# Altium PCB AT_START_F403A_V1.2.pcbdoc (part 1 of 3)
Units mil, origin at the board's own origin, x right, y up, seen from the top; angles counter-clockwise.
Board outline 5262.73 x 3522.74 mil, 2 copper layers (Top Layer, Bottom Layer); 135 components, 162 nets, 647 pads, 293 vias.
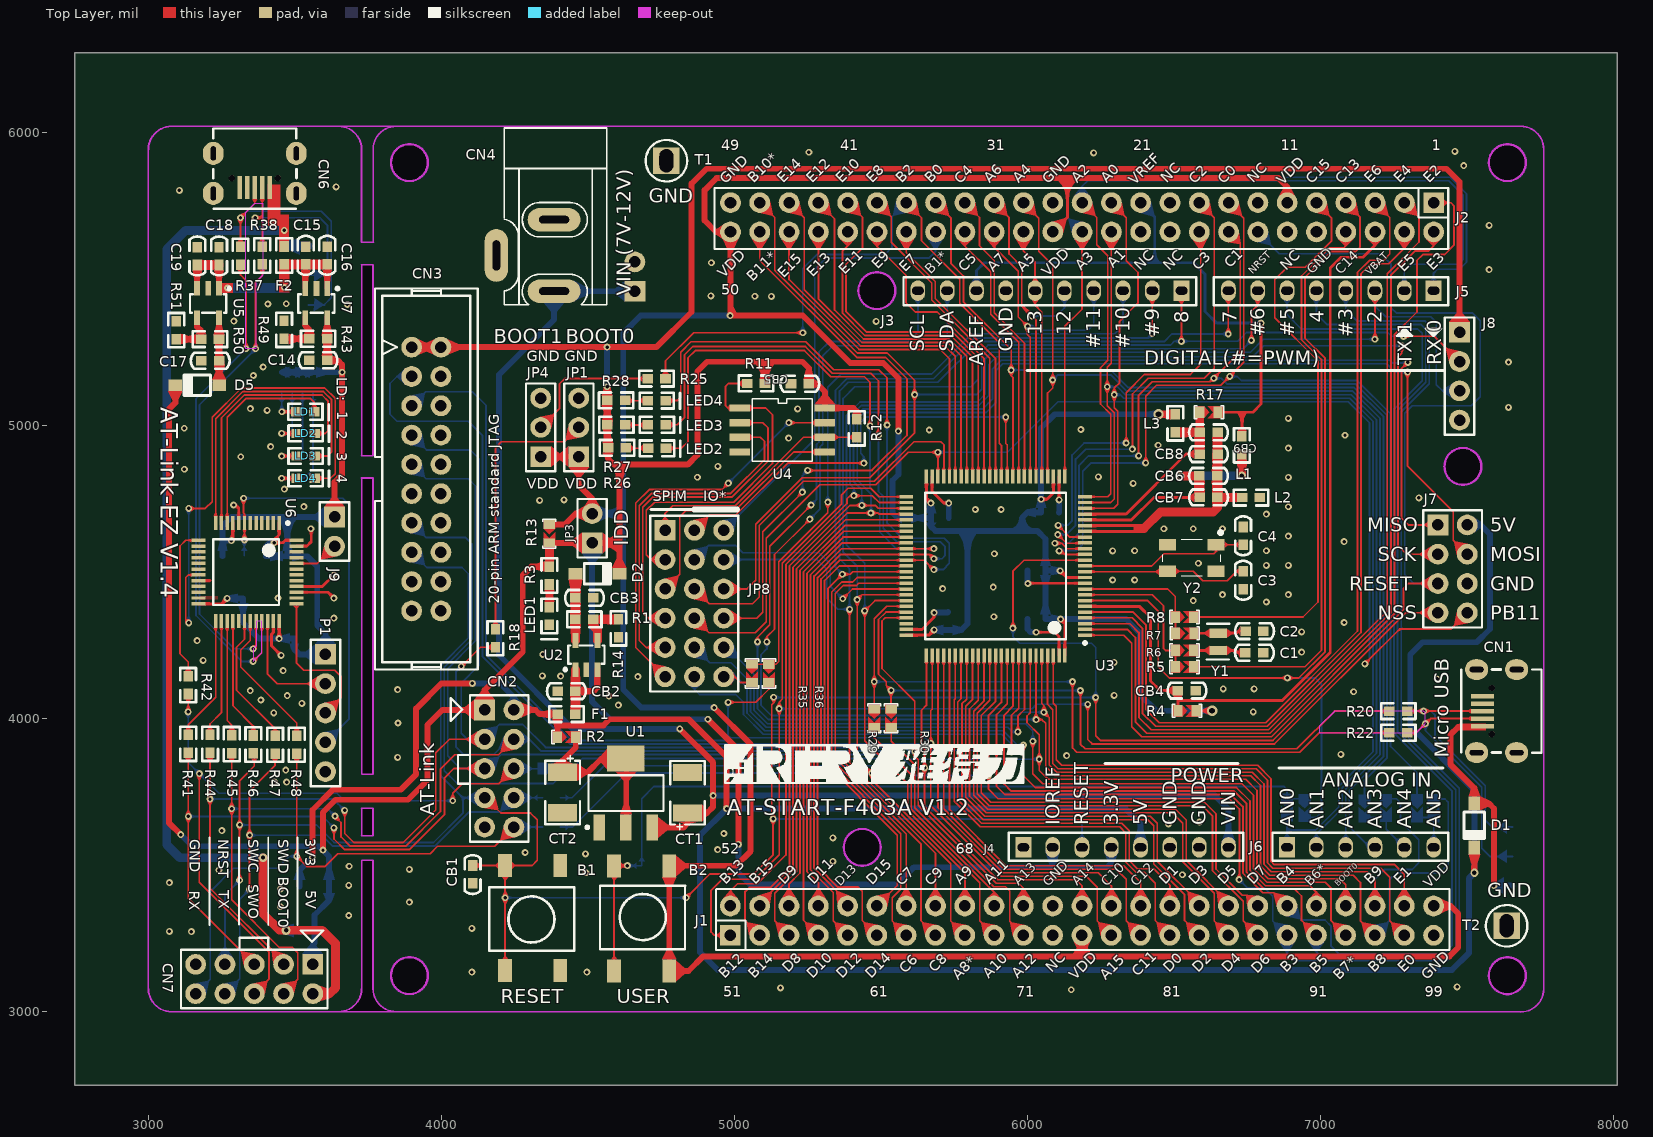
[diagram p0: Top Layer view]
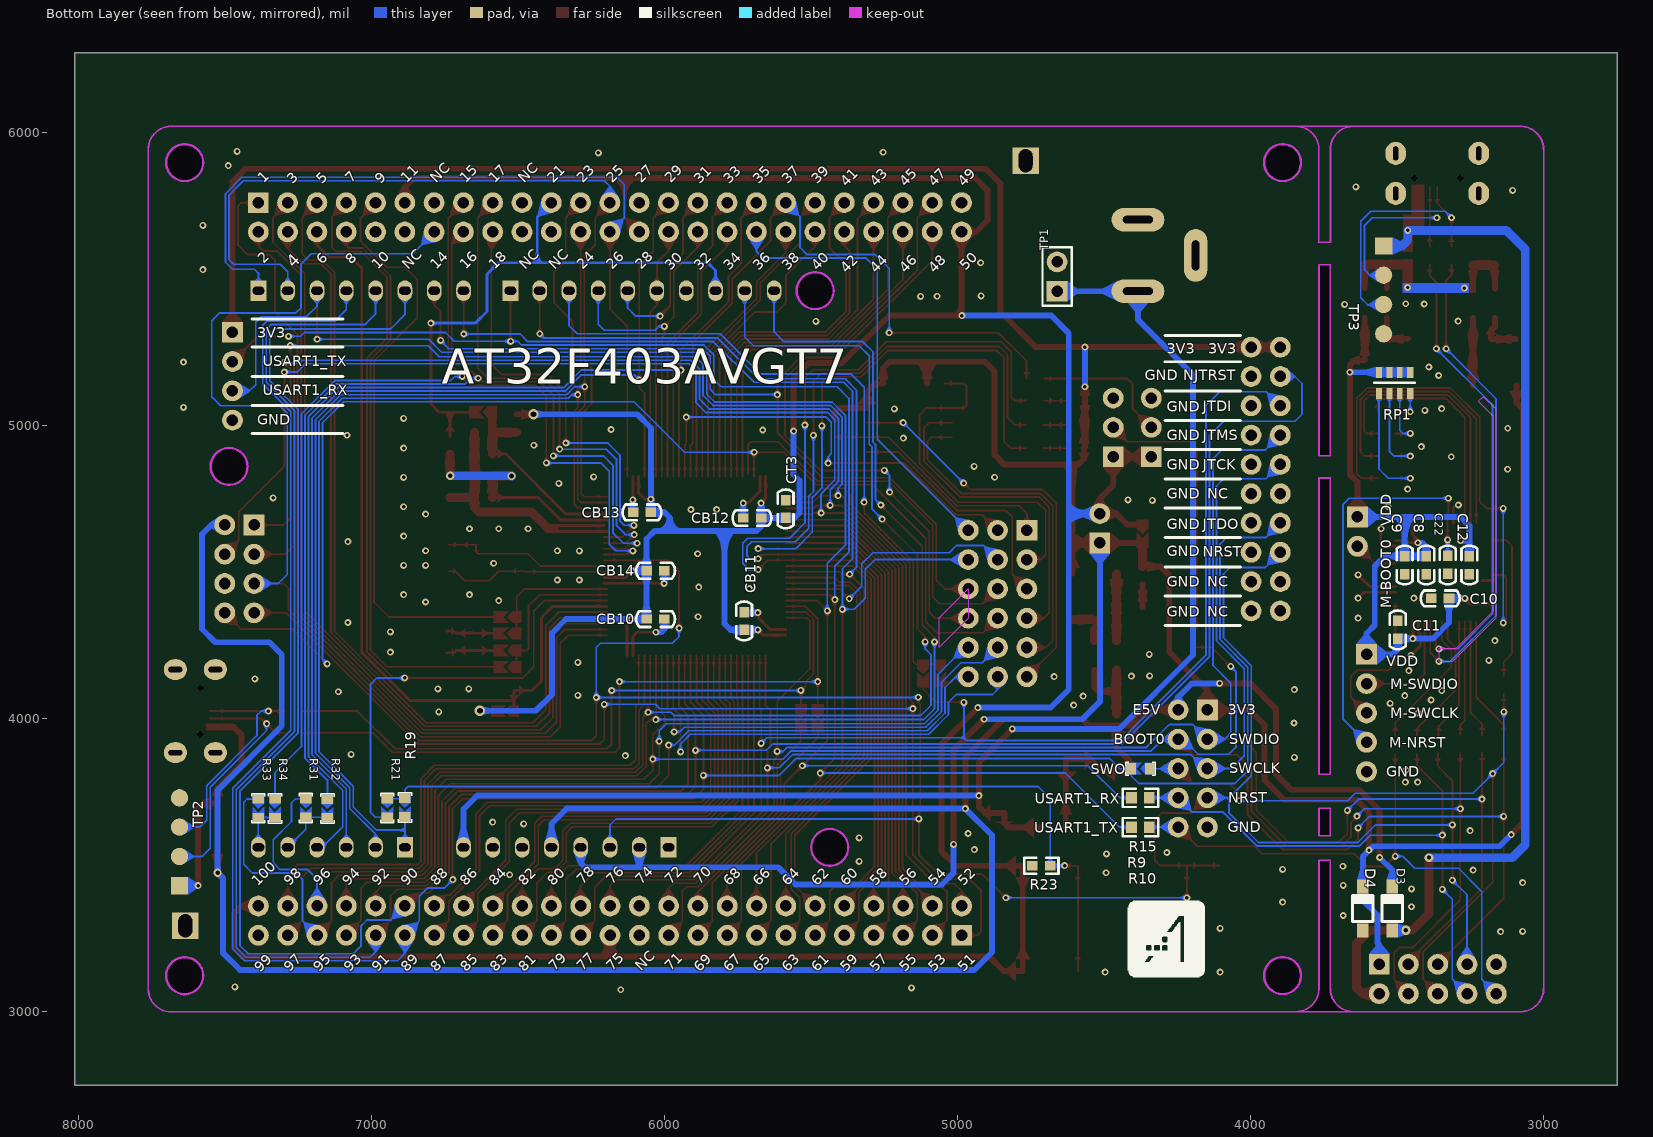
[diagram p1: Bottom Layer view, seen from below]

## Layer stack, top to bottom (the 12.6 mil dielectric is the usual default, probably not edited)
Top Layer: signal copper (thickness not stored)
Dielectric: dielectric 12.6, FR-4, Dk 4.8
Bottom Layer: signal copper (thickness not stored)

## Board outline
8012.73,2750 2750,2750 2750,6272.74 8012.73,6272.74
cut-out: 3728.37,5549.34 3767.37,5549.34 3767.19,5549.16 3767.19,4898.56 3727.68,4898.56
cut-out: 3728.37,4821.34 3767.37,4821.34 3767.37,3811.06 3728.37,3811.06
cut-out: 3728.37,3694.34 3767.37,3694.34 3767.37,3602.34 3728.37,3602.34
cut-out: 3728.11,3518.06 3767.19,3518.06 3767.19,3079.78 3767.63,3079.34 3767.63,3077.95 ccw(c3845.26,3077.95) 3790.37,3023.06 ccw(c3844.58,3077.27) 3844.58,3000.6 3649.37,3000.6 3651.16,3000.6 ccw(c3651.16,3077.27) 3705.37,3023.06 ccw(c3650.47,3077.96) 3728.11,3077.96
cut-out: 3954.07,5896.88 cw(c3891.07,5896.88) 3891.07,5833.89 cw(c3891.07,5898.89) 3826.07,5898.89 3826.07,5903.89 cw(c3886.07,5903.89) 3886.07,5963.89 3891.07,5963.89 cw(c3891.07,5900.9) 3954.07,5900.9
cut-out: 7700.69,5895.58 cw(c7637.7,5895.58) 7637.7,5832.59 cw(c7637.7,5897.59) 7572.7,5897.59 7572.7,5902.59 cw(c7632.7,5902.59) 7632.7,5962.59 7637.7,5962.59 cw(c7637.7,5899.6) 7700.69,5899.6
cut-out: 7701.69,3121.58 cw(c7638.7,3121.58) 7638.7,3058.59 cw(c7638.7,3123.59) 7573.7,3123.59 7573.7,3128.59 cw(c7633.7,3128.59) 7633.7,3188.59 7638.7,3188.59 cw(c7638.7,3125.6) 7701.69,3125.6
cut-out: 3954.07,3121.88 cw(c3891.07,3121.88) 3891.07,3058.89 cw(c3891.07,3123.89) 3826.07,3123.89 3826.07,3128.89 cw(c3886.07,3128.89) 3886.07,3188.89 3891.07,3188.89 cw(c3891.07,3125.9) 3954.07,3125.9
cut-out: 5549.69,5459.58 cw(c5486.7,5459.58) 5486.7,5396.59 cw(c5486.7,5461.59) 5421.7,5461.59 5421.7,5466.59 cw(c5481.7,5466.59) 5481.7,5526.59 5486.7,5526.59 cw(c5486.7,5463.6) 5549.69,5463.6
cut-out: 7549.69,4859.58 cw(c7486.7,4859.58) 7486.7,4796.59 cw(c7486.7,4861.59) 7421.7,4861.59 7421.7,4866.59 cw(c7481.7,4866.59) 7481.7,4926.59 7486.7,4926.59 cw(c7486.7,4863.6) 7549.69,4863.6
cut-out: 5499.69,3559.58 cw(c5436.7,3559.58) 5436.7,3496.59 cw(c5436.7,3561.59) 5371.7,3561.59 5371.7,3566.59 cw(c5431.7,3566.59) 5431.7,3626.59 5436.7,3626.59 cw(c5436.7,3563.6) 5499.69,3563.6

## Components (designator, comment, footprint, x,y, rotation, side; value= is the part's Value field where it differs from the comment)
B1 "PB,BLACK,SMD_2P" KEY_SOP_6*6 4217.99,3140.74 r90 top
B2 "PB,Blue,SMD_2P" KEY_SOP_6*6 4777.99,3498.74 r270 top
C1 "10pF" C0603 6744.03,4225.54 r0 top
C2 "10pF" C0603 6745.03,4299.54 r0 top
C3 "22pF" C0603 6736.99,4504.06 r270 top
C4 "22pF" C0603 6736.99,4594.06 r90 top
C8 "4.7uF/16V" C0603 3400.64,4494.38 r90 bottom
C9 "0.1uF/16V" C0603 3474.64,4494.38 r90 bottom
C10 "0.1uF/16V" C0603 3384.33,4411.14 r180 bottom
C11 "0.1uF/16V" C0603 3498.63,4335.04 r270 bottom
C12 "0.1uF/16V" C0603 3253.64,4494.38 r90 bottom
C14 "10uF" C0603 3610.43,5224.27 r180 top
C15 "10uF" C0603 3537.85,5551.23 r90 top
C16 "0.1uF" C0603 3611.05,5551.27 r90 top
C17 "10uF" C0603 3242.43,5222.34 r180 top
C18 "10uF" C0603 3241.85,5549.23 r90 top
C19 "0.1uF" C0603 3167.85,5549.23 r90 top
C22 "0.1uF/16V" C0603 3327.85,4556.34 r270 bottom
CB1 "0.1uF" C0603 4106.79,3499.7 r270 top
CB2 "1uF" C0603 4457.95,4095.06 r180 top
CB3 "1uF" C0603 4457.99,4412.74 r0 top
CB4 "1uF" C0603 6514.03,4096.54 r0 top
CB5 "0.1uF" C0603 5254.7,5144.17 r180 top
CB6 "1uF" C0603 6587.33,4829.11 r0 top
CB7 "0.1uF" C0603 6587.99,4755.74 r0 top
CB8 "1uF" C0603 6649.33,4904.11 r180 top
CB9 "0.1uF" C0603 6649.33,4978.11 r180 top
CB10 "0.1uF" C0603 6061.99,4340.74 r180 bottom
CB11 "0.1uF" C0603 5728.99,4303.74 r90 bottom
CB12 "0.1uF" C0603 5671.03,4685.94 r0 bottom
CB13 "0.1uF" C0603 6047.03,4704.94 r0 bottom
CB14 "0.1uF" C0603 6061.99,4505.74 r180 bottom
CN1 "USB micro-B" USB_MIC_DIP 7553.06,4026.74 r0 top
CN2 "CON10A" HDR2X5 4147.99,4030.74 r270 top
CN3 "10X2P" JTAG_20 3948.99,4818.74 r270 top
CN4 "DC_JACK" DC10B 4214.99,5878.83 r270 top
CN6 "USB_micro B" USB_MIC_DIP 3363.62,5812.96 r90 top
CN7 "CON1" HDR2X5 3561.85,3162.34 r180 top
CT1 "10uF" C3528 4840.37,3679.06 r90 top
CT2 "10uF" C3528 4414.37,3818.06 r270 top
CT3 "4.7uF" C0603 5587.12,4685.93 r90 bottom
D1 "DFLS130L" SOD-123 7525.99,3636.74 r90 top
D2 "DFLS130L" SOD-123 4532.95,4495.74 r180 top
D3 "DFLS130L" SOD-123 3516.37,3353.06 r270 bottom
D4 "SMF3.3A" SOD-123 3617.37,3353.06 r270 bottom
D5 "DFLS130L" SOD-123 3167.43,5138.34 r0 top
F1 "SMD0603B025TF" r0603 4396.99,4016.06 r0 top
F2 "SMD0603B025TF" r0603 3463.85,5612.23 r270 top
J1 "CONN EDGE 25X2" HEAD2*25 4986.7,3261.59 r0 top
J2 "CONN EDGE 25X2" HEAD2*25 7387.12,5762.02 r180 top
J3 "CON10" "HDR1X10 - 2#" 6526.69,5461.59 r180 top
J4 "CON8" "HDR1X8 - 2#" 5986.69,3561.59 r0 top
J5 "CON8" "HDR1X8 - 2#" 7386.69,5461.59 r180 top
J6 "CON6" "HDR1X6 -2#" 6886.7,3561.59 r0 top
J7 "CON8A" HDR2X4 7401.7,4662.17 r270 top
J8 "Header 4" HDR1X4 7475.29,5319.74 r270 top
J9 "1X2P_2.54M" HDR1X2 3635.85,4689.34 r270 top
JP1 "1X3P_2.54M" HDR1X3 4469.37,4895.06 r90 top
JP3 "1X2P_2.54M" HDR1X2 4514.99,4600.76 r90 top
JP4 "1X3P_2.54M" HDR1X3 4339.37,4895.06 r90 top
JP8 "CON3*6" HDR3X6 4763.99,4643.74 r270 top
L1 "BEAD" r0603 6732.33,4964.11 r270 top
L2 "BEAD" r0603 6793.99,4755.74 r180 top
L3 "BEAD" r0603 6505.33,5039.11 r270 top
LD1 "RED" LED0603 3505.89,5048.14 r0 top
LD2 "GREEN" LED0603 3506.85,4974.04 r0 top
LD3 "BLUE" LED0603 3506.89,4897.14 r0 top
LD4 "YELLOW" LED0603 3506.85,4821.14 r0 top
LED1 "RED" LED0603 4368.99,4381.77 r270 top
LED2 "RED" LED0603 4706.03,4923.17 r0 top
LED3 "YELLOW" LED0603 4705.42,5003.94 r0 top
LED4 "GREEN" LED0603 4705.03,5086.17 r0 top
P1 "Header 5" HDR1X5 3604.85,4220.34 r270 top
R1 "51K" r0603 4518.95,4339.94 r180 top
R2 "0R" SB-PAD 4427.37,3938.06 r0 top
R3 "1K" r0603 4368.79,4519.7 r270 top
R4 "0R" SB-PAD 6545.46,4027.64 r0 top
R5 "NC" SB-PAD 6537,4177.64 r0 top
R6 "0R" SB-PAD 6537.03,4233.74 r0 top
R7 "0R" SB-PAD 6537.48,4292.24 r0 top
R8 "NC" SB-PAD 6536.52,4347.66 r0 top
R9 "470R" 0603_R 4376.46,3730.66 r0 bottom
R10 "470R" 0603_R 4376.46,3630.66 r0 bottom
R11 "NC" r0603 5043.99,5144.74 r0 top
R12 "NC" r0603 5418.57,4961.09 r90 top
R13 "0R" SB-PAD 4368.99,4632.06 r270 top
R14 "15K" r0603 4605.2,4278.78 r90 top
R15 "0R" SB-PAD 4376.46,3830.16 r0 bottom
R17 "0R" SB-PAD 6619.83,5046.64 r0 top
R18 "10K" r0603 4184.79,4305.7 r270 top
R19 "0R" SB-PAD 6886.77,3697.91 r270 bottom
R20 "22R" r0603 7296.95,4026.94 r180 top
R21 "NC" SB-PAD 6947.07,3696.21 r270 bottom
R22 "22R" r0603 7296.99,3952.74 r180 top
R23 "100K" r0603 4744.95,3498.88 r180 bottom
R25 "100K" r0603 4765.33,5161.74 r180 top
R26 "1K" r0603 4569.33,4924.74 r0 top
R27 "1K" r0603 4567.33,5003.74 r0 top
R28 "1K" r0603 4566.33,5086.74 r0 top
R29 "NC" SB-PAD 5477.74,4002.23 r270 top
R30 "NC" SB-PAD 5535.37,4002.15 r270 top
R31 "NC" SB-PAD 7224.98,3696.17 r270 bottom
R32 "0R" SB-PAD 7151.3,3694.23 r270 bottom
R33 "NC" SB-PAD 7387.07,3695.21 r270 bottom
R34 "0R" SB-PAD 7330.14,3694.97 r270 bottom
R35 "NC" SB-PAD 5060.47,4155.52 r270 top
R36 "0R" SB-PAD 5118.37,4155.06 r270 top
R37 "22R" r0603 3314.64,5611.19 r270 top
R38 "22R" r0603 3388.64,5612.15 r270 top
R41 "33R" r0603 3137.05,3884.38 r90 top
R42 "33R" r0603 3136.37,4085.06 r90 top
R43 "47K" r0603 3549.47,5297.06 r0 top
R44 "33R" r0603 3211.05,3884.38 r90 top
R45 "33R" r0603 3285.05,3883.38 r90 top
R46 "33R" r0603 3359.05,3882.38 r90 top
R47 "33R" r0603 3433.05,3881.38 r90 top
R48 "33R" r0603 3507.05,3881.38 r90 top
R49 "15K" r0603 3463.22,5358.23 r270 top
R50 "51K" r0603 3180.47,5296.14 r0 top
R51 "15K" r0603 3095.22,5357.3 r270 top
RP1 "1K" RP_4-0603 3562.23,5110.22 r90 bottom
T1 "Socket" TestPoint 4768.37,5905.06 r90 top
T2 "Socket" TestPoint 7636.06,3294.06 r90 top
TP1 "1X2P_2.54M" HDR1X2 4660.99,5459.74 r90 bottom
TP2 "1X4P_2.54F" "HDR1X4 - top" 7655.99,3430.74 r90 bottom
TP3 "1X4P_2.54F" "HDR1X4 - top" 3546.43,5614.34 r270 bottom
U1 "AMS1117-5.0" SOT223 4630.29,3747.06 r90 top
U2 "RT9080N-08GJ5" SOT-23-5 4557.99,4232.74 r90 top
U3 "AT32F403AVGT7" LQFP100_14*14 5892.03,4522.06 r180 top
U4 "EN25QH128A" SOIC8_208 5164.37,4986.06 r270 top
U5 "RT9080N-08GJ5" SOT-23-5 3141.64,5404.23 r270 top
U6 "AT32F403ACCT7" LQFP48_7*7 3338.32,4501.21 r270 top
U7 "RT9080N-08GJ5" SOT-23-5 3510.85,5404.16 r270 top
Y1 "32.768KHz" "XTAL_SOP - FC-12M" 6651.99,4292.74 r270 top
Y2 "8MHz" SMD_5032_4P 6561.37,4549.06 r180 top

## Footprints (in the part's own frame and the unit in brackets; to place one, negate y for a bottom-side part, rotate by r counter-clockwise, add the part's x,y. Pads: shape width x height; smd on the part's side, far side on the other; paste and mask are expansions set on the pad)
0603_R [mm]
  rect 0.93x0.98 smd mask+0.051: 1(-0.77,0) 2(0.77,0)
  silkscreen extent -1.53,-0.79 1.54,0.79
C0603 [mil]
  rect 36x32 smd mask+2: 1(-0.04,0.2) 2(60.96,0.2)
  silkscreen extent -35,-27 97,27
C3528 [mm]
  rect 1.5x2.5 smd mask+0.051: 1(0,0) 2(3.5,0)
  silkscreen extent -1.45,-1.5 4.5,1.5
DC10B [mil]
  oval 80x180 hole 25.59 slot 102.36 at 90 deg mask+2: 1(419.09,170) 2(175,170)
  oval 180x80 hole 25.59 slot 102.36 at 0 deg mask+2: 3(297.05,-26.85)
  silkscreen extent -138,0 465,350
HDR1X2 [mm]
  rect 1.8x1.8 hole 1 mask+0.051: 1(0,0)
  round 1.8 hole 1 mask+0.051: 2(2.54,0)
  silkscreen extent -1.27,-1.27 3.81,1.27
HDR1X3 [mm]
  rect 1.8x1.8 hole 1 mask+0.051: 1(0,0)
  round 1.8 hole 1 mask+0.051: 2(2.54,0) 3(5.08,0)
  silkscreen extent -1.27,-1.27 6.35,1.27
HDR1X4 [mm]
  rect 1.8x1.8 hole 1 mask+0.051: 1(0,0)
  round 1.8 hole 1 mask+0.051: 2(2.54,0) 3(5.08,0) 4(7.62,0)
  silkscreen extent -1.27,-1.27 8.89,1.27
"HDR1X4 - top" [mm]
  rect 1.5x1.5 smd mask+0.051: 1(0,0)
  round 1.5 smd mask+0.051: 2(2.54,0) 3(5.08,0) 4(7.62,0)
HDR1X5 [mm]
  rect 1.8x1.8 hole 1 mask+0.051: 1(0,0)
  round 1.8 hole 1 mask+0.051: 2(2.54,0) 3(5.08,0) 4(7.62,0) 5(10.16,0)
  silkscreen extent -1.27,-1.27 11.43,1.27
"HDR1X6 -2#" [mil]
  rect 55x70 hole 27.56 slot 39.37 at 0 deg mask+2: 1(0,0)
  oval 50x70 hole 27.56 slot 39.37 at 0 deg mask+2: 2(100,0) 3(200,0) 4(300,0) 5(400,0) 6(500,0)
  silkscreen extent -50,-46 550,50
"HDR1X8 - 2#" [mil]
  rect 55x70 hole 27.56 slot 39.37 at 0 deg mask+2: 1(0,0)
  oval 50x70 hole 27.56 slot 39.37 at 0 deg mask+2: 2(100,0) 3(200,0) 4(300,0) 5(400,0) 6(500,0) 7(600,0) 8(700,0)
  silkscreen extent -50,-46 750,50
"HDR1X10 - 2#" [mil]
  rect 55x70 hole 27.56 slot 39.37 at 0 deg mask+2: 1(0,0)
  oval 50x70 hole 27.56 slot 39.37 at 0 deg mask+2: 2(100,0) 3(200,0) 4(300,0) 5(400,0) 6(500,0) 7(600,0) 8(700,0) 9(800,0) 10(900,0)
  silkscreen extent -50,-46 949,50
HDR2X4 [mm]
  rect 1.8x1.8 hole 1 mask+0.051: 1(0,0)
  round 1.8 hole 1 mask+0.051: 2(0,2.54) 3(2.54,0) 4(2.54,2.54) 5(5.08,0) 6(5.08,2.54) 7(7.62,0) 8(7.62,2.54)
  silkscreen extent -1.27,-1.27 8.89,3.81
HDR2X5 [mm]
  rect 1.8x1.8 hole 1 mask+0.051: 1(0,0)
  round 1.8 hole 1 mask+0.051: 2(0,2.54) 3(2.54,0) 4(2.54,2.54) 5(5.08,0) 6(5.08,2.54) 7(7.62,0) 8(7.62,2.54) 9(10.16,0) 10(10.16,2.54)
  silkscreen extent -1.27,-1.27 11.43,3.81
HDR3X6 [mm]
  rect 1.8x1.8 hole 1 mask+0.051: 1(0,0)
  round 1.8 hole 1 mask+0.051: 2(0,2.54) 3(0,5.08) 4(2.54,0) 5(2.54,2.54) 6(2.54,5.08) 7(5.08,0) 8(5.08,2.54) 9(5.08,5.08) 10(7.62,0) 11(7.62,2.54) 12(7.62,5.08) 13(10.16,0) 14(10.16,2.54) 15(10.16,5.08) 16(12.7,0) 17(12.7,2.54) 18(12.7,5.08)
  silkscreen extent -1.27,-1.3 13.97,6.35
HEAD2*25 [mm]
  rect 1.8x1.8 hole 1 mask+0.051: 1(0,0)
  round 1.8 hole 1 mask+0.051: 2(0,2.54) 3(2.54,0) 4(2.54,2.54) 5(5.08,0) 6(5.08,2.54) 7(7.62,0) 8(7.62,2.54) 9(10.16,0) 10(10.16,2.54) 11(12.7,0) 12(12.7,2.54) 13(15.24,0) 14(15.24,2.54) 15(17.78,0) 16(17.78,2.54) 17(20.32,0) 18(20.32,2.54) 19(22.86,0) 20(22.86,2.54) 21(25.4,0) 22(25.4,2.54) 23(27.94,0) 24(27.94,2.54) 25(30.48,0) 26(30.48,2.54) 27(33.02,0) 28(33.02,2.54) 29(35.56,0) 30(35.56,2.54) 31(38.1,0) 32(38.1,2.54) 33(40.64,0) 34(40.64,2.54) 35(43.18,0) 36(43.18,2.54) 37(45.72,0) 38(45.72,2.54) 39(48.26,0) 40(48.26,2.54) 41(50.8,0) 42(50.8,2.54) 43(53.34,0) 44(53.34,2.54) 45(55.88,0) 46(55.88,2.54) 47(58.42,0) 48(58.42,2.54) 49(60.96,0) 50(60.96,2.54)
  silkscreen extent -1.26,-1.26 62.36,4
JTAG_20 [mm]
  round 1.8 hole 1 mask+0.051: 1(-11.43,-1.27) 2(-11.43,1.27) 3(-8.89,-1.27) 4(-8.89,1.27) 5(-6.35,-1.27) 6(-6.35,1.27) 7(-3.81,-1.27) 8(-3.81,1.27) 9(-1.27,-1.27) 10(-1.27,1.27) 11(1.27,-1.27) 12(1.27,1.27) 13(3.81,-1.27) 14(3.81,1.27) 15(6.35,-1.27) 16(6.35,1.27) 17(8.89,-1.27) 18(8.89,1.27) 19(11.43,-1.27) 20(11.43,1.27)
  silkscreen extent -16.51,-4.45 16.51,4.44
KEY_SOP_6*6 [mm]
  rect 2x1.2 smd mask+0.051: 1(0,0) 1(9.119,0) 2(0,-4.775) 2(9.119,-4.775)
  silkscreen extent 1.73,-5.99 7.24,1.4
LED0603 [mil]
  rect 36x32 smd mask+2: 1(-0.04,0.2) 2(60.96,0.2)
  silkscreen extent -28,-28 110,27
LQFP48_7*7 [mm]
  rect 1.2x0.3 smd mask+0.051: 1(-4.25,2.75) 2(-4.25,2.25) 3(-4.25,1.75) 4(-4.25,1.25) 5(-4.25,0.75) 6(-4.25,0.25) 7(-4.25,-0.25) 8(-4.25,-0.75) 9(-4.25,-1.25) 10(-4.25,-1.75) 11(-4.25,-2.25) 12(-4.25,-2.75) 25(4.25,-2.75) 26(4.25,-2.25) 27(4.25,-1.75) 28(4.25,-1.25) 29(4.25,-0.75) 30(4.25,-0.25) 31(4.25,0.25) 32(4.25,0.75) 33(4.25,1.25) 34(4.25,1.75) 35(4.25,2.25) 36(4.25,2.75)
  rect 0.3x1.2 smd mask+0.051: 13(-2.75,-4.25) 14(-2.25,-4.25) 15(-1.75,-4.25) 16(-1.25,-4.25) 17(-0.75,-4.25) 18(-0.25,-4.25) 19(0.25,-4.25) 20(0.75,-4.25) 21(1.25,-4.25) 22(1.75,-4.25) 23(2.25,-4.25) 24(2.75,-4.25) 37(2.75,4.25) 38(2.25,4.25) 39(1.75,4.25) 40(1.25,4.25) 41(0.75,4.25) 42(0.25,4.25) 43(-0.25,4.25) 44(-0.75,4.25) 45(-1.25,4.25) 46(-1.75,4.25) 47(-2.25,4.25) 48(-2.75,4.25)
  silkscreen extent -4.37,-2.96 2.86,3.64
LQFP100_14*14 [mm]
  rect 1.2x0.3 smd mask+0.051: 1(-7.75,6) 2(-7.75,5.5) 3(-7.75,5) 4(-7.75,4.5) 5(-7.75,4) 6(-7.75,3.5) 7(-7.75,3) 8(-7.75,2.5) 9(-7.75,2) 10(-7.75,1.5) 11(-7.75,1) 12(-7.75,0.5) 13(-7.75,0) 14(-7.75,-0.5) 15(-7.75,-1) 16(-7.75,-1.5) 17(-7.75,-2) 18(-7.75,-2.5) 19(-7.75,-3) 20(-7.75,-3.5) 21(-7.75,-4) 22(-7.75,-4.5) 23(-7.75,-5) 24(-7.75,-5.5) 25(-7.75,-6) 51(7.75,-6) 52(7.75,-5.5) 53(7.75,-5) 54(7.75,-4.5) 55(7.75,-4) 56(7.75,-3.5) 57(7.75,-3) 58(7.75,-2.5) 59(7.75,-2) 60(7.75,-1.5) 61(7.75,-1) 62(7.75,-0.5) 63(7.75,0) 64(7.75,0.5) 65(7.75,1) 66(7.75,1.5) 67(7.75,2) 68(7.75,2.5) 69(7.75,3) 70(7.75,3.5) 71(7.75,4) 72(7.75,4.5) 73(7.75,5) 74(7.75,5.5) 75(7.75,6)
  rect 0.3x1.2 smd mask+0.051: 26(-6,-7.75) 27(-5.5,-7.75) 28(-5,-7.75) 29(-4.5,-7.75) 30(-4,-7.75) 31(-3.5,-7.75) 32(-3,-7.75) 33(-2.5,-7.75) 34(-2,-7.75) 35(-1.5,-7.75) 36(-1,-7.75) 37(-0.5,-7.75) 38(0,-7.75) 39(0.5,-7.75) 40(1,-7.75) 41(1.5,-7.75) 42(2,-7.75) 43(2.5,-7.75) 44(3,-7.75) 45(3.5,-7.75) 46(4,-7.75) 47(4.5,-7.75) 48(5,-7.75) 49(5.5,-7.75) 50(6,-7.75) 76(6,7.75) 77(5.5,7.75) 78(5,7.75) 79(4.5,7.75) 80(4,7.75) 81(3.5,7.75) 82(3,7.75) 83(2.5,7.75) 84(2,7.75) 85(1.5,7.75) 86(1,7.75) 87(0.5,7.75) 88(0,7.75) 89(-0.5,7.75) 90(-1,7.75) 91(-1.5,7.75) 92(-2,7.75) 93(-2.5,7.75) 94(-3,7.75) 95(-3.5,7.75) 96(-4,7.75) 97(-4.5,7.75) 98(-5,7.75) 99(-5.5,7.75) 100(-6,7.75)
  silkscreen extent -7.88,-6.35 6.09,6.8
r0603 [mil]
  rect 36x32 smd mask+2: 1(-0.04,0.2) 2(60.96,0.2)
  silkscreen extent -28,-27 89,27
RP_4-0603 [mm]
  rect 0.95x0.55 smd mask+0.051: 1(0,-2.7) 4(0,0) 5(1.85,0) 8(1.85,-2.7)
  rect 0.95x0.5 smd mask+0.051: 2(0,-1.8) 3(0,-0.9) 6(1.85,-0.9) 7(1.85,-1.8)
  silkscreen extent 0.94,-3.1 0.94,0.43
SB-PAD [mm]
  rect 0.8x1 smd paste+0.102 mask+0.102: 1(-0.799,0.003) 2(0.799,0.002)
  Top Layer region: -1.2,-0.5 -1.2,0.5 -0.418,0.5 0.025,0 -0.433,-0.5
  Top Layer region: -0.119,0.5 0.381,0 -0.119,-0.5 1.2,-0.5 1.2,0.5
  silkscreen extent -1.28,-0.58 1.28,0.58
SMD_5032_4P [mm]
  rect 1.5x1 smd mask+0.051: 1(-2.1,-1.15) 2(2.1,-1.15) 3(2.1,1.15) 4(-2.1,1.15)
  silkscreen extent -2.65,-2.35 2.5,1.6
SOD-123 [mm]
  rect 1.2x1 smd mask+0.051: 1(1.905,0) 2(-1.905,0)
  silkscreen extent -1.14,-0.89 1.14,0.89
SOIC8_208 [mil]
  rect 25x70 smd paste+4 mask+2: 1(-75,-145) 2(-25,-145) 3(25,-145) 4(75,-145) 5(75,145) 6(25,145) 7(-25,145) 8(-75,145)
  silkscreen extent -106,-102 106,102
SOT223 [mm]
  rect 2.25x1 smd mask+0.051: 1(-2.975,2.3) 2(-2.975,0) 3(-2.975,-2.3)
  rect 2.25x3.25 smd mask+0.051: 4(2.975,0)
  silkscreen extent -3.1,-3.25 1.55,3.47
SOT-23-5 [mil]
  rect 50x20 smd mask+2: 1(-65,100) 2(-65,63) 3(-65,25) 4(35,25) 5(35,100)
  silkscreen extent -65,1 18,135
TestPoint [mm]
  rect 2.3x2.3 hole 1.2 slot 2 at 0 deg mask+0.051: 1(0,0)
  silkscreen extent -1.8,-1.8 1.8,1.8
USB_MIC_DIP [mm]
  rect 2x0.4 smd mask+0.051: 1(0,-1.3) 2(0,-0.65) 3(0,0) 4(0,0.65) 5(0,1.3)
  oval 2x1.8 hole 0.45 slot 1.2 at 0 deg mask+0.051: 6(-0.495,-3.6) 7(2.975,-3.6) 8(2.975,3.6) 9(-0.495,3.6)
  round 0.5 hole 0.55 unplated mask+0.051: MH1(0.825,2) MH2(0.825,-2)
  silkscreen extent -1.82,-3.6 5.12,3.6
"XTAL_SOP - FC-12M" [mm]
  rect 0.8x1.5 smd mask+0.051: 1(0,0) 2(1.5,0)
  silkscreen extent -0.81,-0.99 2.29,0.94

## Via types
v1: diameter 23.62, hole 11.81, Top Layer to Bottom Layer, 286 vias
v2: diameter 28, hole 16, Top Layer to Bottom Layer, 3 vias
v3: diameter 35, hole 20, Top Layer to Bottom Layer, 2 vias
v4: diameter 29.53, hole 13.78, Top Layer to Bottom Layer, 1 vias
v5: diameter 31.5, hole 15.75, Top Layer to Bottom Layer, 1 vias

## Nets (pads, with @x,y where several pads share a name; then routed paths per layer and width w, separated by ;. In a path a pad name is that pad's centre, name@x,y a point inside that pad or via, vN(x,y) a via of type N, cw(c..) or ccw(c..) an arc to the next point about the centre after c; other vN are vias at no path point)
3V3: CB5.1 CN2.1 CN3.1 CN3.2 CN7.1 D2.2 D4.2 D5.2 J4.2 J4.4 J8.1 JP3.1 R3.1 R11.2 R12.2 R13.2 R26.1 R27.1 R28.1 U4.8 | length 14105.3
  Top Layer w20: D5.2@3092.43,5138.34 3092.43,5079.11 3070.37,5057.06 3070.37,3645.82 v1(3110.85,3605.34) ; v1(3596.37,3552.34) 3596.37,3681.06 3639.37,3724.06 3886.34,3724.06 3952.86,3790.57 3952.86,3979.83 4003.77,4030.74 CN2.1@4147.99,4030.74 4147.99,4098.74 4277.99,4228.74 4277.99,4490.74 4306.99,4519.74 R3.1@4368.99,4519.74 ; CN3.1@3898.99,5268.74 CN3.2@3998.99,5268.74 4733.99,5268.74 4853.99,5388.74 4853.99,5826.74 4904.99,5877.74 7430.99,5877.74 7475.29,5833.44 J8.1@7475.29,5319.74 ; R13.2@4369.25,4600.76 JP3.1@4514.99,4600.76 4607.92,4600.76 ; v1(4566.29,5133.74) R28.1@4566.29,5086.94 4566.29,4927.94 R26.1@4569.29,4924.94 4569.29,4888.85 4590.37,4867.76 4606.98,4867.76 ; D2.2@4607.95,4495.74 4607.95,4600.8 4607.95,4866.79 4606.98,4867.76 ; v1(4909.99,3998.74) 5013.99,3894.74 v1(5013.99,3572.06) ; R11.2@5104.95,5144.94 5104.95,5218.94 ; R12.2@5418.37,5022.06 5418.37,5049.06 5406.37,5061.06 U4.8@5309.37,5061.06 5309.37,5116.13 5281.53,5143.96 CB5.1@5254.74,5143.96 5254.74,5197 5232.79,5218.94 5104.95,5218.94 ; 4606.98,4867.76 4841.02,4867.76 4873.99,4900.74 4873.99,5186.06 4906.88,5218.94 5104.95,5218.94
  Top Layer w30: R3.1@4368.99,4519.74 R13.2@4368.99,4600.51
  Bottom Layer w20: v1(3110.85,3605.34) 3150.85,3565.34 3582.37,3565.34 3617.37,3530.34 D4.2@3617.37,3428.06 3617.37,3381.06 3567.37,3331.06 3567.37,3235.06 3561.37,3229.06 3561.37,3162.82 CN7.1@3561.85,3162.34 ; JP3.1@4514.99,4600.76 4514.99,4058.77 4575.02,3998.74 v1(4909.99,3998.74) ; v1(4566.29,5133.74) v1(4566.29,5268.97) ; v1(5013.99,3572.06) 5013.99,3474.74 5053.99,3434.74 5553.99,3434.74 5612.99,3493.74 6085.4,3493.74 6086.69,3495.04 J4.2@6086.69,3561.59 ; 6086.69,3493.74 6271.99,3493.74 6286.69,3508.44 J4.4@6286.69,3561.59
5V: CN2.2 D1.2 D3.2 F1.1 J4.5 J7.2 R2.1 | length 9028.6
  Top Layer w20: v1(3560.37,3527.06) 3560.37,3689.34 3629.37,3758.34 3861.65,3758.34 3914.37,3811.06 3914.37,4035.06 4000.37,4121.06 v1(4106.37,4121.06) ; CN2.2@4247.99,4030.74 4321.68,4030.74 4336.16,4016.26 F1.1@4396.95,4016.26 ; R2.1@4396.99,3939.25 F1.1@4396.95,4016.26 ; 4397.99,3978.06 4553.68,3978.06 4574.37,3998.74 4844.99,3998.74 4973.99,3869.74 v1(4973.99,3693.74) ; v2(7525.99,3474.74) D1.2@7525.99,3561.74
  Bottom Layer w20: D3.2@3516.37,3428.06 3516.37,3483.06 v1(3560.37,3527.06) ; v1(4106.37,4121.06) 4201.37,4121.06 4247.99,4074.43 CN2.2@4247.99,4030.74 ; J4.5@6386.69,3561.59 6386.69,3642.04 6334.99,3693.74 v1(4973.99,3693.74) 4882.99,3602.74 4882.99,3203.74 4943.99,3142.74 7448.99,3142.74 7506.99,3200.74 7506.99,3455.74 v2(7525.99,3474.74) 7525.99,3756.74 7306.99,3975.74 7306.99,4219.74 7348.99,4261.74 7533.99,4261.74 7578.99,4306.74 7578.99,4630.74 7547.57,4662.17 J7.2@7501.7,4662.17
$1N750: LD1.1 RP1.1 | length 111.5
  Top Layer w6: v1(3456.37,5048.34) LD1.1@3505.85,5048.34
  Bottom Layer w6: RP1.1@3455.94,5110.22 3455.94,5048.77 v1(3456.37,5048.34)
$1N751: LD2.1 RP1.2 | length 217.4
  Top Layer w6: v1(3455.37,4974.24) LD2.1@3506.81,4974.24
  Bottom Layer w6: v1(3455.37,4974.24) 3481.04,4974.24 3491.37,4984.58 RP1.2@3491.37,5110.22
$1N752: LD3.1 RP1.3 | length 326.6
  Top Layer w6: v1(3455.37,4897.06) 3506.56,4897.06 LD3.1@3506.85,4897.34
  Bottom Layer w6: v1(3455.37,4897.06) 3510.37,4897.06 3526.8,4913.49 RP1.3@3526.8,5110.22
$1N753: LD4.1 RP1.4 | length 428.7
  Top Layer w6: v1(3455.37,4821.34) LD4.1@3506.81,4821.34
  Bottom Layer w6: v1(3455.37,4821.34) 3530.65,4821.34 3562.23,4852.92 RP1.4@3562.23,5110.22
$1N764: C15.1 C16.1 C18.1 C19.1 F2.2 U5.1 U5.3 U7.1 U7.3 | length 541.8
  Top Layer w20: U5.3@3166.64,5469.23 3166.64,5548.19 C19.1@3167.64,5549.19 ; U5.1@3241.64,5469.23 C18.1@3241.64,5549.19 ; U7.3@3535.85,5471.23 C15.1@3535.85,5549.4 ; U7.1@3610.85,5471.23 C16.1@3610.85,5551.23
  Top Layer w30: C19.1@3167.64,5549.19 C18.1@3241.64,5549.19 ; F2.2@3464.05,5551.27 3537.64,5551.27 C16.1@3610.81,5551.27 ; C15.1@3535.85,5549.4 C15.1@3537.64,5551.19
  other v1: 3270.85,5470.34 3464.85,5472.34
$1N902: R50.1 R51.2 U5.4 | length 163.6
  Top Layer w20: R51.2@3095.43,5296.34 R50.1@3180.43,5296.34 3180.43,5324.34 3166.64,5338.12 U5.4@3166.64,5369.23
$1N903: R43.1 R49.2 U7.4 | length 163.5
  Top Layer w20: R49.2@3463.43,5297.27 R43.1@3549.43,5297.27 3549.43,5328.27 3535.85,5341.85 U7.4@3535.85,5369.16
$2N606: JP4.2 R25.2 | length 483.2
  Top Layer w6: JP4.2@4339.37,4995.06 4403.37,5059.06 4403.37,5143.06 4421.85,5161.54 R25.2@4704.37,5161.54
$2N607: C2.1 R7.2 Y1.1 | length 179.1
  Top Layer w10: R7.2@6568.95,4292.31 6651.57,4292.31 Y1.1@6651.99,4292.74 6714.02,4292.74 6721.02,4299.74 C2.1@6744.99,4299.74
$2N616: R7.1 R8.1 U3.9 | length 444.3
  Top Layer w6: U3.9@6197.15,4443.31 6479.42,4443.31 6505.06,4417.67 R8.1@6505.06,4347.77 6506.02,4346.81 R7.1@6506.02,4292.34
$2N617: C4.1 U3.13 Y2.1 | length 583.5
  Top Layer w6: U3.13@6197.15,4522.06 6424.99,4522.06 6466.61,4563.67 6636.99,4563.67 6644.05,4570.73 Y2.1@6644.05,4594.33 6736.47,4594.33 C4.1@6736.79,4594.02
$2N619: C3.1 U3.12 Y2.3 | length 567.5
  Top Layer w6: U3.12@6197.15,4502.37 6477.28,4502.37 Y2.3@6478.69,4503.78 6566.64,4503.78 6598.93,4471.49 6682.12,4471.49 6714.72,4504.09 C3.1@6737.2,4504.09
$2N629: C1.1 R6.2 Y1.2 | length 178.8
  Top Layer w10: R6.2@6568.5,4233.82 6651.86,4233.82 Y1.2@6651.99,4233.69 6711.99,4233.69 6719.94,4225.74 C1.1@6743.99,4225.74
$2N642: R5.1 R6.1 U3.8 | length 528
  Top Layer w6: U3.8@6197.15,4423.63 6427.1,4423.63 6464.99,4385.74 6464.99,4240.74 6471.89,4233.84 R6.1@6505.56,4233.84 ; R5.1@6505.53,4177.74 R6.1@6505.53,4233.81
$2N666: JP1.2 R18.1 | length 933.1
  Top Layer w6: R18.1@4184.99,4305.74 4184.99,4925.74 4204.99,4945.74 4420.05,4945.74 JP1.2@4469.37,4995.06
$3N664: LED1.1 R3.2 | length 77
  Top Layer w20: R3.2@4368.99,4458.74 4368.99,4382.02 LED1.1@4369.2,4381.81
$3N671: CB3.1 D2.1 R1.2 U2.5 | length 228
  Top Layer w30: U2.5@4457.99,4267.74 R1.2@4457.99,4339.74 CB3.1@4457.95,4412.94 D2.1@4457.95,4495.74
$3N672: CT2.1 R2.2 U1.2 U1.4 | length 607.2
  Top Layer w20: R2.2@4458.84,3938.13 4458.84,3902.52 4414.37,3858.06 CT2.1@4414.37,3818.06 4500.37,3818.06 4545.18,3862.87 4631.29,3862.87 U1.2@4631.29,3629.61
$3N673: CB2.1 F1.2 U2.1 U2.3 | length 291.8
  Top Layer w20: CB2.1@4457.99,4094.85 4520.16,4094.85 4532.99,4107.68 U2.3@4532.99,4167.74
  Top Layer w30: F1.2@4457.95,4016.26 CB2.1@4457.95,4094.81 ; CB2.1@4457.99,4094.85 U2.1@4457.99,4167.74
$3N822: B2.2 R19.1 R21.1 R23.2 | length 2996.1
  Top Layer w6: B2.2@4589.99,3139.74 B2.2@4589.99,3498.74 4590.34,3499.09 v1(4634.99,3499.09)
  Bottom Layer w6: v1(4634.99,3499.09) R23.2@4683.99,3499.09 4683.99,3727.74 4725.99,3769.74 6874.99,3769.74 6886.67,3758.06 R19.1@6886.67,3729.38 ; R19.1@6886.67,3727.67 R21.1@6946.97,3727.67 ; R19.1@6886.97,3729.67 R19.1@6887.26,3729.38
$3N825: LED3.1 R27.2 | length 88.1
  Top Layer w6: R27.2@4617.29,5002.94 LED3.1@4705.42,5002.94
$3N826: LED4.1 R28.2 | length 89.3
  Top Layer w6: R28.2@4616.29,5085.94 4703.57,5086.94 4704.57,5085.94 LED4.1@4704.99,5086.37
$3N833: LED2.1 R26.2 | length 87.4
  Top Layer w6: R26.2@4619.29,4923.94 4704.42,4924.94 LED2.1@4705.99,4923.37
$3N837: R1.1 R14.2 U2.4 | length 140.8
  Top Layer w30: R1.1@4518.99,4339.74 4518.99,4317.74 4532.99,4303.74 U2.4@4532.99,4267.74 ; 4541.99,4339.74 R14.2@4604.99,4339.74
$4N292: J1.21 R30.2 | length 919.2
  Top Layer w6: R30.2@5535.45,3970.68 5535.45,3923.98 5616.18,3843.24 5616.18,3696.55 5885.64,3427.09 5925.64,3427.09 5939.99,3412.74 5939.99,3309.15 J1.21@5987.12,3262.02
$4N319: J1.20 R29.2 | length 778.3
  Top Layer w6: R29.2@5477.75,3970.76 5477.75,3936.39 5604.18,3809.96 5604.18,3691.58 5887.12,3408.64 J1.20@5887.12,3362.02
A0: J2.23 J6.1 R19.2 U3.23 | length 3822.1
  Top Layer w6: U3.23@6197.15,4718.91 6295.16,4718.91 6308.84,4732.59 6308.84,5049.83 6296.99,5061.68 v1(6296.99,5106.74) 6296.99,5129.74 6314.99,5147.74 6314.99,5356.74 6377.99,5419.74 6377.99,5523.74 6337.99,5563.74 6337.99,5710.29 J2.23@6286.7,5761.59
  Bottom Layer w6: v1(6296.99,5106.74) 6316.99,5106.74 6328.99,5094.74 7100.96,5094.74 7179.99,5015.71 7179.99,3887.95 7062.7,3770.65 7062.7,3699.42 6984.02,3620.74 6886.7,3620.74 ; J6.1@6886.7,3561.59 6886.7,3620.74 ; R19.2@6886.99,3666.74 R19.2@6886.7,3666.44 6886.7,3620.74
A1: J2.24 J6.2 U3.24 | length 3541.2
  Top Layer w6: U3.24@6197.15,4738.59 6284.84,4738.59 6296.84,4750.59 6296.84,5044.86 6272.99,5068.71 v1(6272.99,5133.74) 6272.99,5200.04 6286.7,5213.74 J2.24@6286.7,5661.59
  Bottom Layer w6: v1(6272.99,5133.74) 6307.99,5133.74 6334.99,5106.74 7105.93,5106.74 7191.99,5020.68 7191.99,3882.98 7074.7,3765.68 7074.7,3694.44 6986.7,3606.44 J6.2@6986.7,3561.59
A2: J2.29 J6.3 U3.29 | length 3681.7
  Top Layer w6: J2.29@5986.7,5761.59 6038.99,5709.29 6038.99,5595.74 6086.69,5548.04 v1(6086.69,5156.74) 6086.69,5129.44 6069.2,5111.94 U3.29@6069.2,4827.17
  Bottom Layer w6: v1(6086.69,5156.74) 6104.01,5174.06 6284.65,5174.06 6339.96,5118.74 7110.9,5118.74 7203.99,5025.65 7203.99,3878.01 7086.7,3760.71 J6.3@7086.7,3561.59
A3: J2.35 J6.4 U3.35 | length 3945.9
  Top Layer w6: J2.35@5687.12,5762.02 5739.99,5709.14 5739.99,5553.74 5781.99,5511.74 5781.99,5423.74 5944.99,5260.74 v1(5944.99,5190.74) 5944.99,5171.83 5951.09,5165.74 U3.35@5951.09,4827.17
  Bottom Layer w6: v1(5944.99,5190.74) 6284.93,5190.74 6344.93,5130.74 7115.87,5130.74 7215.99,5030.62 7215.99,3873.04 7098.7,3755.74 7098.7,3632.04 7169.14,3561.59 J6.4@7186.7,3561.59
A4: J6.5 R31.2 R32.2 | length 202.8
  Bottom Layer w6: R32.2@7151.2,3664.7 R31.2@7224.9,3664.7 ; R31.2@7224.9,3665.13 R31.2@7224.9,3664.7 ; J6.5@7286.7,3561.59 7224.9,3623.39 R31.2@7224.9,3664.7
A5: J6.6 R33.2 R34.2 | length 159.3
  Bottom Layer w6: R34.2@7330.07,3663.51 7386.76,3663.51 R33.2@7386.99,3663.74 7386.99,3561.89 J6.6@7386.7,3561.59
ATLINK_5V: CN6.1 CN7.2 D3.1 F2.1 TP3.1 | length 3693.5
  Top Layer w30: v4(3391.85,3526.34) 3391.85,3335.58 3448.37,3279.06 v5(3470.37,3279.06) 3593.37,3279.06 3639.37,3233.06 3639.37,3083.06 3618.65,3062.34 CN7.2@3561.85,3062.34
  Bottom Layer w30: v4(3391.85,3526.34) 3108.08,3526.34 3063.37,3571.06 3063.37,5602.86 3127.85,5667.34 v1(3464.05,5667.34) 3464.05,5633.71 3483.43,5614.34 TP3.1@3546.43,5614.34 ; v5(3470.37,3279.06) 3515.37,3279.06 D3.1@3516.37,3278.06
ATLK_BOOT0: R45.2 U6.27 | length 395.7
  Top Layer w6: U6.27@3269.42,4333.69 3269.42,3994.46 3284.85,3979.04 R45.2@3284.85,3944.34
ATLK_NRST: R46.2 U6.28 | length 419.2
  Top Layer w6: U6.28@3289.11,4333.69 3289.11,4045.2 3358.85,3975.46 R46.2@3358.85,3943.34
ATLK_RX: CN2.10 CN7.10 R10.1 R48.1 | length 1973.9
  Top Layer w6: R48.1@3506.85,3881.34 v1(3506.85,3531.05) 3541.85,3496.06 3602.37,3496.06 3646.37,3540.06 3962.25,3540.06 3987.25,3565.06 4182.31,3565.06 CN2.10@4247.99,3630.74
  Bottom Layer w6: CN7.10@3161.85,3062.34 3211.37,3111.86 3211.37,3410.34 3291.08,3490.06 3440.37,3490.06 3481.37,3531.05 v1(3506.85,3531.05) ; CN2.10@4247.99,3630.74 R10.1@4346.14,3630.66
ATLK_SWCLK: R41.2 U6.25 | length 427
  Top Layer w6: R41.2@3136.85,3945.34 3136.85,3980.53 3230.05,4073.74 U6.25@3230.05,4333.69
ATLK_SWDIO: R44.2 U6.26 | length 404.5
  Top Layer w6: R44.2@3210.85,3945.34 3210.85,3982.53 3249.74,4021.42 U6.26@3249.74,4333.69
ATLK_SWO: R42.2 U6.13 | length 526.2
  Top Layer w6: R42.2@3136.16,4146.02 3136.16,4194.26 3108.37,4222.06 3108.37,4590.06 3127.79,4609.48 U6.13@3171,4609.48
ATLK_TX: CN2.8 CN7.8 R9.1 R47.1 | length 1973.8
  Top Layer w6: v1(3345.85,3418.34) v1(3345.85,3603.34) 3345.85,3754.29 3432.85,3841.29 R47.1@3432.85,3881.34
  Bottom Layer w6: CN7.8@3261.85,3062.34 3312.37,3112.86 3312.37,3384.86 v1(3345.85,3418.34) ; v1(3345.85,3603.34) 3592.14,3603.34 3629.43,3566.06 3978.37,3566.06 4094.37,3682.06 4199.31,3682.06 CN2.8@4247.99,3730.74 R9.1@4346.14,3730.66
AVREF+: J2.21 J3.8 L1.1 R17.2 | length 1952.7
  Top Layer w10: R17.2@6651.3,5046.71 6732.99,5046.71 ; L1.1@6732.53,4964.15 6732.99,4964.61 6732.99,5046.71 ; v1(6797.99,5350.74) 6797.99,5074.71 6769.99,5046.71 6732.99,5046.71
  Bottom Layer w10: J3.8@5826.69,5461.59 5826.69,5530.44 5852.99,5556.74 6434.99,5556.74 ; J2.21@6386.7,5761.59 6434.99,5713.29 6434.99,5556.74 ; v1(6797.99,5350.74) 6646.99,5350.74 6606.99,5390.74 6606.99,5517.74 6567.99,5556.74 6434.99,5556.74
BOOT0: CN2.4 CN7.4 J1.44 R18.2 R45.1 U3.94 | length 6566.5
  Top Layer w6: R45.1@3284.85,3883.34 v1(3284.85,3693.34) 3284.85,3382.34 3447.13,3220.06 3492.37,3220.06 3510.37,3202.06 3510.37,3110.86 CN7.4@3461.85,3062.34 ; v1(3637.37,3668.06) 3637.37,3666.82 3657.85,3646.34 3657.85,3597.34 3689.13,3566.06 3879.05,3566.06 3997.05,3684.06 3997.05,3828.43 4046.68,3878.06 4195.31,3878.06 CN2.4@4247.99,3930.74 ; v1(4068.37,4179.06) 4134.05,4244.74 R18.2@4184.99,4244.74 ; U3.94@6010.14,4216.94 6010.14,4021.28 5998.99,4010.13 5998.99,3987.61 6040.86,3945.74 6040.86,3823.87 6070.99,3793.74 6745.99,3793.74 6783.99,3755.74 6783.99,3493.86 6823.11,3454.74 7065.99,3454.74 7086.7,3434.04 J1.44@7086.7,3361.59
  Bottom Layer w6: v1(3284.85,3693.34) 3612.08,3693.34 v1(3637.37,3668.06) ; v1(4068.37,4179.06) 4049.99,4160.68 4049.99,3904.74 4074.99,3879.74 4180.02,3879.74 4231.02,3930.74 CN2.4@4247.99,3930.74 4299.99,3930.74 4339.99,3890.74 5568.34,3890.74 5596.34,3862.74 v1(6040.99,3862.74)
D0_RX: J2.26 J5.1 U3.26 | length 2857.1
  Top Layer w6: U3.26@6128.25,4827.17 6128.25,5340 6186.7,5398.44 J2.26@6186.7,5661.59
  Bottom Layer w6: J2.26@6186.7,5661.59 6137.99,5710.29 6137.99,5823.74 6162.99,5848.74 7442.96,5848.74 7498.99,5792.71 7498.99,5558.74 7474.99,5534.74 7399.99,5534.74 7386.69,5521.44 J5.1@7386.69,5461.59
D1_TX: J2.25 J5.2 U3.25 | length 3032.8
  Top Layer w6: J2.25@6186.7,5761.59 6236.99,5711.29 6236.99,5618.74 6274.7,5581.04 6274.7,5223.44 6249.99,5198.74 6249.99,5074.74 6284.84,5039.89 6284.84,4768.59 6274.53,4758.28 U3.25@6197.15,4758.28
  Bottom Layer w6: J2.25@6186.7,5761.59 6186.7,5817.44 6205.99,5836.74 7437.99,5836.74 7486.99,5787.74 7486.99,5567.74 7470.99,5551.74 7311.99,5551.74 7286.69,5526.44 J5.2@7286.69,5461.59
D2: J1.19 J5.3 J8.3 R9.2 U3.69 | length 6041.5
  Top Layer w6: U3.69@5586.91,4403.94 5480.2,4403.94 v1(5444.99,4368.74) 5444.99,3925.43 v1(5530.37,3840.06) 5592.18,3778.24 5592.18,3686.61 5837.99,3440.8 5837.99,3311.15 J1.19@5887.12,3262.02 ; v1(7186.69,5295.74) J5.3@7186.69,5461.59
  Bottom Layer w6: R9.2@4406.77,3730.59 4446.37,3730.59 4555.84,3840.06 v1(5530.37,3840.06) ; v1(5444.99,4368.74) 5444.99,4531.34 5383.37,4592.96 5383.37,5036.06 5429.05,5081.74 5829.99,5081.74 5856.99,5108.74 5856.99,5229.74 5878.99,5251.74 6761.99,5251.74 6805.99,5295.74 v1(7186.69,5295.74) ; J5.3@7186.69,5461.59 7186.69,5409.04 7222.99,5372.74 7376.99,5372.74 7395.99,5353.74 7395.99,5140.74 7416.99,5119.74 J8.3@7475.29,5119.74
D3: CN3.13 J1.39 J5.4 R15.2 U3.89 | length 8179.8
  Top Layer w6: v1@5867.99,3807.06 5867.99,3759.8 5900.05,3727.74 6688.99,3727.74 6723.99,3692.74 6723.99,3452.74 v1(6722.99,3451.74) ; v1@5867.99,3816.74 5867.99,4012.74 5911.72,4056.46 U3.89@5911.72,4216.94
  Bottom Layer w6: CN3.13@3898.99,4668.74 3948.99,4618.74 4082.99,4618.74 4104.99,4596.74 4104.99,4271.71 4009.99,4176.71 4009.99,3823.74 4053.99,3779.74 4382.42,3779.74 4407.93,3805.24 R15.2@4407.93,3830.08 4446.37,3830.08 4481.17,3864.88 5553.23,3864.88 5611.05,3807.06 v1(5868.37,3807.06) ; v1(6722.99,3451.74) 6751.99,3422.74 6809.99,3422.74 6837.99,3394.74 6837.99,3310.3 J1.39@6886.7,3261.59 6886.7,3200.04 6911.99,3174.74 7433.96,3174.74 7473.99,3214.77 7473.99,3763.62 7275.99,3961.62 7275.99,5047.86 7371.99,5143.86 7371.99,5343.74 7357.99,5357.74 7125.99,5357.74 7086.69,5397.04 J5.4@7086.69,5461.59
D4: J1.41 J5.5 U3.91 | length 5174.6
  Top Layer w6: U3.91@5951.09,4216.94 5951.09,4042.83 5920.99,4012.74 5920.99,3777.74 5944.99,3753.74 6705.99,3753.74 6747.99,3711.74 6747.99,3478.95 6808.2,3418.74 6912.99,3418.74 6935.99,3395.74 6935.99,3312.3 J1.41@6986.7,3261.59
  Bottom Layer w6: J1.41@6986.7,3261.59 6986.7,3206.04 7005.99,3186.74 7428.99,3186.74 7461.99,3219.74 7461.99,3758.65 7263.99,3956.65 7263.99,5052.83 7359.99,5148.83 7359.99,5329.74 7343.99,5345.74 7023.99,5345.74 6986.69,5383.04 J5.5@6986.69,5461.59
D5: CN3.3 J1.40 J5.6 U3.90 | length 8394
  Top Layer w6: U3.90@5931.4,4216.94 5931.4,4051.15 5894.99,4014.74 v1(5894.99,3892.74) 5894.99,3770.74 5923.99,3741.74 6694.99,3741.74 6735.99,3700.74 6735.99,3473.98 6803.23,3406.74 6841.55,3406.74 J1.40@6886.7,3361.59
  Bottom Layer w6: CN3.3@3898.99,5168.74 3848.99,5168.74 3824.99,5144.74 3824.99,5039.74 3848.99,5015.74 4091.99,5015.74 4140.99,4966.74 4140.99,4212.74 4438.99,3914.74 5630.68,3914.74 5652.68,3892.74 v1(5894.99,3892.74) ; J1.40@6886.7,3361.59 6934.55,3313.74 7015.99,3313.74 7036.99,3292.74 7036.99,3224.74 7062.99,3198.74 7421.99,3198.74 7449.99,3226.74 7449.99,3753.68 7251.99,3951.68 7251.99,5057.8 7347.99,5153.8 7347.99,5315.74 7332.99,5330.74 6934.99,5330.74 6886.69,5379.04 J5.6@6886.69,5461.59
D6: J2.47 J5.7 JP8.9 | length 3519.2
  Top Layer w6: JP8.9@4963.99,4443.74 5043.64,4443.74 5073.37,4473.47 5073.37,4665.03 5231.4,4823.06 5461.77,4823.06 5615.37,4976.65 v1(5615.37,5107.06) 5615.37,5155.06 5521.68,5248.74 5419.99,5248.74 5137.99,5530.74 5137.99,5711.14 J2.47@5087.12,5762.02 ; v1(6764.99,5291.74) 6764.99,5390.74 6786.69,5412.44 J5.7@6786.69,5461.59
  Bottom Layer w6: v1(5615.37,5107.06) 5827.31,5107.06 5844.99,5124.74 5844.99,5237.74 5870.99,5263.74 6736.99,5263.74 v1(6764.99,5291.74)
D7: J1.17 J5.8 JP8.6 | length 4333.1
  Top Layer w6: v1(5393.45,4374.06) 5393.45,3851.4 5738.99,3505.86 5738.99,3310.15 J1.17@5787.12,3262.02 ; v1(6685.99,5313.74) 6685.99,5460.29 6686.99,5461.29 J5.8@6686.69,5461.59
  Bottom Layer w6: v1(6685.99,5313.74) 6492.99,5313.74 6466.99,5287.74 5833.99,5287.74 5694.99,5148.74 5389.37,5148.74 5359.37,5118.74 5359.37,4546.13 5393.45,4512.06 v1(5393.45,4374.06) 5353.37,4374.06 5315.37,4412.06 5315.37,4510.74 5282.37,4543.74 5149.46,4543.74 ; 5149.46,4543.74 JP8.6@4963.99,4543.74 4964.49,4543.24 5148.96,4543.24 5149.46,4543.74
D8: J1.18 J3.1 J8.2 R10.2 U3.68 | length 5665
  Top Layer w6: U3.68@5586.91,4423.63 5435.94,4423.63 v1(5419.37,4407.06) 5419.37,3865.06 v1(5469.37,3815.06) 5469.37,3792.45 5787.12,3474.7 J1.18@5787.12,3362.02 ; v1(6525.99,5288.74) 6525.99,5460.29 6526.99,5461.29 J3.1@6526.69,5461.59 ; v1(7283.99,5305.74) 7389.29,5305.74 J8.2@7475.29,5219.74
  Bottom Layer w6: R10.2@4406.77,3630.66 4447.99,3630.74 4632.31,3815.06 v1(5469.37,3815.06) ; 5419.37,4420.06 5419.37,4521.06 5371.37,4569.06 5371.37,5093.74 5411.37,5133.74 5807.99,5133.74 5832.99,5158.74 5832.99,5242.71 5866.02,5275.74 6488.99,5275.74 6501.99,5288.74 v1(6525.99,5288.74) 6718.29,5288.74 6748.29,5318.74 7229.99,5318.74 7242.99,5305.74 v1(7283.99,5305.74)
D9: J1.14 J3.2 U3.64 | length 3462.7
  Top Layer w6: J1.14@5580.4,3377.66 5570.63,3377.66 J1.14@5586.7,3361.59 5586.7,3607.24 5320.37,3873.57 5320.37,4445.31 v1(5368.8,4493.74) 5396.05,4493.74 5404.68,4502.37 U3.64@5586.91,4502.37 ; v1(6426.69,5314.44) J3.2@6426.69,5461.59
  Bottom Layer w6: v1(5368.8,4493.74) 5345.37,4517.17 5345.37,5121.71 5384.4,5160.74 5679.99,5160.74 5818.99,5299.74 6411.99,5299.74 v1(6426.69,5314.44)
D10: J3.3 R35.1 R36.1 | length 2313.8
  Top Layer w6: R35.1@5060.57,4186.99 R36.1@5118.01,4186.99 ; R36.1@5118.47,4186.52 5142.46,4186.52 5151.99,4196.06 5151.99,4536.72 5319.37,4704.1 v1(5319.37,4740.06)
  Bottom Layer w6: v1(5319.37,4740.06) 5319.37,5132.06 5364.05,5176.74 5672.99,5176.74 5810.99,5314.74 6298.99,5314.74 6326.69,5342.44 J3.3@6326.69,5461.59
D11: J2.32 J3.4 U3.32 | length 1239.9
  Top Layer w6: J2.32@5886.7,5661.59 5886.7,5610.04 5968.99,5527.74 5968.99,5371.74 v1(6000.99,5339.74) 6000.99,5311.74 6010.14,5302.59 U3.32@6010.14,4827.17
  Bottom Layer w6: v1(6000.99,5339.74) 6019.99,5339.74 6032.99,5326.74 6206.99,5326.74 6226.69,5346.44 J3.4@6226.69,5461.59
D12: J2.31 J3.5 U3.31 | length 1175
  Top Layer w6: J2.31@5886.7,5761.59 5937.99,5710.29 5937.99,5586.74 5980.99,5543.74 5980.99,5410.65 6029.83,5361.82 U3.31@6029.83,4827.17
  Bottom Layer w6: v1(6015.99,5374.74) 6098.99,5374.74 6126.69,5402.44 J3.5@6126.69,5461.59
D13: J2.30 J3.6 U3.30 | length 860.4
  Top Layer w6: J2.30@5986.7,5661.59 5986.7,5598.04 6026.69,5558.04 J3.6@6026.69,5461.59 6026.69,5411.74 6049.51,5388.92 U3.30@6049.51,4827.17
GND: B1.2 C1.2 C2.2 C3.2 C4.2 C8.1 C9.1 C10.1 C11.1 C12.1 C14.2 C15.2 C16.2 C17.2 C18.2 C19.2 C22.2 CB1.2 CB2.2 CB3.2 CB4.2 CB5.2 CB10.2 CB11.2 CB12.2 CB13.2 CB14.2 CN1.5 CN1.6 CN1.7 CN1.8 CN1.9 CN2.9 CN3.4 CN3.6 CN3.8 CN3.10 CN3.12 CN3.14 CN3.16 CN3.18 CN3.20 CN4.2 CN4.3 CN6.5 CN6.6 CN6.7 CN6.8 CN6.9 CN7.9 CT1.2 CT2.2 CT3.2 D4.1 J1.24 J1.49 J2.10 J2.27 J2.49 J3.7 J4.6 J4.7 J7.6 J8.4 JP1.3 JP4.3 L2.1 LED1.2 P1.5 R14.1 R23.1 R49.1 R51.1 T1.1 T2.1 TP1.2 TP2.4 TP3.4 U1.1 U2.2 U3.10 U3.27 U3.49 U3.74 U3.99 U4.4 U5.2 U6.8 U6.20 U6.23 U6.35 U6.39 U6.40 U6.47 U7.2 | length 1569.2
  Top Layer w10: U6.20@3171,4471.69 3211.37,4471.69 ; v1(3291.37,4730.06) 3298.22,4730.06 3308.79,4719.48 U6.8@3308.79,4668.34 ; U6.35@3426.9,4333.89 3426.9,4294.59 3421.22,4288.9 3421.22,4249.13 v1(3453.37,4216.98) ; U6.39@3505.64,4432.31 3613.97,4432.31 v1(3633.85,4412.43) ; U6.40@3505.64,4452 3594.19,4452 v1(3633.85,4491.65) ; U6.47@3505.64,4589.8 3541.37,4589.8 3556.37,4604.8 3556.37,4647.53 v1(3554.85,4649.06) ; U3.74@5586.91,4305.52 5640.77,4305.52 5681.99,4346.74 v1(5681.99,4362.74) ; U3.49@5675.49,4827.17 5675.49,4776.24 5714.99,4736.74 v1(5731.99,4736.74) ; v1(6001.99,4462.17) 6002.83,4463 U3.10@6206.99,4463 ; v1(6029.99,4295.74) 6094.49,4295.74 6108.57,4281.66 U3.99@6108.57,4216.94 ; U3.27@6108.57,4827.17 6108.57,4748.17 v1(6108.99,4747.74)
  Bottom Layer w20: v1(5681.99,4362.74) 5727.24,4362.74 CB11.2@5729.2,4364.7 ; CB12.2@5731.99,4685.74 v1(5731.99,4736.74) ; CB10.2@6001.03,4340.94 6001.03,4306.7 6011.99,4295.74 v1(6029.99,4295.74) ; CB14.2@6001.03,4505.94 6001.03,4463.13 v1(6001.99,4462.17) ; CB13.2@6107.99,4704.74 6108.99,4705.74 v1(6108.99,4747.74)
  other v1: 6149.99,3075.74 5157.88,3081.74 7466.99,3085.74 4104.37,3135.74 4496.99,3135.74 3147.37,3274.06 3072.37,3275.06 4104.37,3285.06 3684.37,3329.06 3451.37,3359.06 3891.07,3375.06 3451.37,3420.06 3684.37,3432.06 3072.37,3441.01 6529.27,3468.06 4493.37,3474.9 3241.37,3483.81 3891.37,3486.64 3685.23,3497.06 5336.37,3514.06 4492.37,3539.06 4286.37,3544.06 4943.37,3554.06 5336.37,3594.06 4964.37,3609.02 3251.55,3618.88 6481.37,3642.06 6587.12,3648.06 3430.68,3784.06 3472.02,3784.06 3469.37,3825 3851.37,3868.68 6134.37,3875.06 7070.06,3878.87 3852.37,3986.06 3428.37,4020.34 6771.37,4024.06 4604.37,4046.98 3524.37,4052.74 3384.37,4064.6 4571.99,4077.74 3474.37,4079.23 6296.37,4080.06 7113.99,4092.74 3348.16,4096.74 3851.37,4100.06 6668.99,4102.74 6774.37,4102.74 7398.99,4136.82 4671.37,4144.06 4407.37,4146.06 4345.37,4147.06 3460.37,4165.06 6296.37,4193.06 3187.37,4200.06 4346.37,4220.34 6936.37,4228.06 3166.64,4267.06 6936.37,4297.06 7081.37,4329.06 3633.85,4344.06 5885.99,4348.74 6816.37,4399.06 6566.37,4404.06 3443.37,4412.06 6666.37,4424.06 6891.37,4424.06 5710.99,4444.74 5883.99,4449.74 6291.37,4474.06 6366.37,4474.06 6816.37,4524.06 6891.37,4524.06 6583.77,4531.34 5887.99,4563.67 6291.37,4573.74 6366.37,4574.06 6816.37,4574.06 7081.37,4605.06 6891.37,4624.06 6466.37,4649.06 6566.37,4649.06 6666.37,4649.06 6816.37,4699.06 5822.99,4714.74 5910.99,4714.74 3531.37,4724.48 6891.37,4724.06 4335.99,4745.74 4418.99,4747.74 7336.37,4754.06 3464.37,4784.06 6361.37,4804.06 6891.37,4824.06 4874.38,4824.74 6242.99,4826.23 3123.59,4852.06 4944.37,4862.06 3315.85,4894.78 6891.37,4924.06 3417.37,4929.06 6446.37,4934.06 5185.37,4958.06 7084.37,4968.06 5665.37,4986.06 6182.99,4987.74 3122.91,4992.06 6891.37,5025.65 3405.8,5053.06 5216.37,5058.06 3348.37,5059.06 7642.37,5063.06 3358.85,5172.06 3391.85,5201.06 7642.37,5218.06 3292.22,5357.34 5484.2,5357.06 3679.37,5415.06 3408.37,5416.06 3471.09,5417.06 5126.81,5442.06 5070.37,5442.63 4919.99,5443.74 7575.99,5533.74 4921.99,5556.74 7575.99,5684.58 3106.37,5804.06 3641.37,5816.06 7489.8,5888.06 6226.37,5932.06 5254.72,5934.06 7459.12,5937.06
